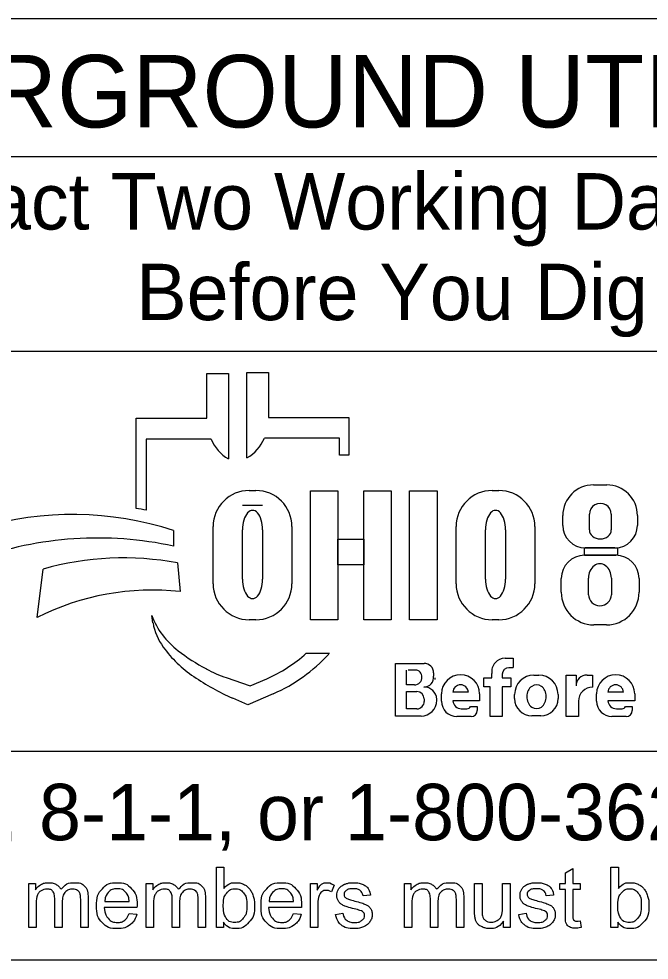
# Model space of a CAD drawing. Extents: x 0 to 36.5, y 0 to 25.3.
# Drawn here: x 3.267 to 4.831, y 2.143 to 4.48 of the extents above; entities that cross this region are included whole.
import ezdxf

# ---------------------------------------------------------------- set-up
doc = ezdxf.new("R2010")
doc.units = 0
doc.layers.add('SH_Data', color=7, linetype='Continuous')
doc.layers.add('SH_Text', color=7, linetype='Continuous')

msp = doc.modelspace()

# ---------------------------------------------------------------- linework, layer by layer
at = {"layer": 'SH_Data'}
for p, q in [((6.6275, 4.4803), (2.3775, 4.4803)), ((2.3775, 4.1387), (6.6275, 4.1387)), ((2.3775, 3.6553), (6.6275, 3.6553)), ((6.6275, 2.6607), (2.3775, 2.6607)), ((6.6275, 2.1428), (2.3775, 2.1428))]:
    msp.add_line(p, q, dxfattribs=at)
at = {"layer": 'SH_Text'}
for p, q in [((3.7335, 3.4883), (3.7335, 3.5998)), ((3.7335, 3.5998), (3.7872, 3.5998)), ((3.7872, 3.5998), (3.7872, 3.3877)), ((3.8329, 3.39), (3.8329, 3.6021)), ((3.8329, 3.6021), (3.8865, 3.6021)), ((3.8865, 3.6021), (3.8865, 3.4906)), ((3.5576, 3.2644), (3.5576, 3.4883)), ((3.5576, 3.4883), (3.7335, 3.4883)), ((3.8865, 3.4906), (4.0857, 3.4906)), ((4.0857, 3.4906), (4.0857, 3.3968)), ((3.5828, 3.4369), (3.5828, 3.26)), ((3.7439, 3.4369), (3.5828, 3.4369)), ((4.0625, 3.4392), (3.8761, 3.4392)), ((4.0625, 3.3968), (4.0625, 3.4392)), ((4.0857, 3.3968), (4.0625, 3.3968)), ((4.6931, 3.3231), (4.7258, 3.3231)), ((3.8385, 3.3091), (3.8551, 3.3091)), ((4.4416, 3.3091), (4.4581, 3.3091)), ((3.8718, 3.2721), (3.822, 3.2721)), ((4.683, 3.2111), (4.683, 3.2504)), ((4.7371, 3.2504), (4.7371, 3.2111)), ((4.6168, 3.2225), (4.6168, 3.2468)), ((4.8022, 3.2468), (4.8022, 3.2225)), ((3.6509, 3.2097), (3.6509, 3.1709)), ((3.7491, 3.0776), (3.7491, 3.2196)), ((3.822, 3.089), (3.822, 3.2114)), ((3.8718, 3.2114), (3.8718, 3.089)), ((3.9445, 3.2196), (3.9445, 3.0776)), ((4.3521, 3.0776), (4.3521, 3.2196)), ((4.425, 3.089), (4.425, 3.2114)), ((4.4748, 3.2114), (4.4748, 3.089)), ((4.5476, 3.2196), (4.5476, 3.0776)), ((4.7462, 3.1665), (4.6728, 3.1665)), ((4.671, 3.1482), (4.7483, 3.1482)), ((3.312, 2.9936), (3.3267, 3.1137)), ((3.6608, 3.1291), (3.6671, 3.0582)), ((4.6131, 3.0563), (4.6131, 3.0903)), ((4.6806, 3.0503), (4.6806, 3.0912)), ((4.7374, 3.0912), (4.7374, 3.0503)), ((4.8062, 3.0903), (4.8062, 3.0563)), ((3.5997, 2.9807), (3.5967, 2.9986)), ((3.8551, 2.9882), (3.8385, 2.9882)), ((4.4581, 2.9882), (4.4416, 2.9882)), ((4.7252, 2.9753), (4.6941, 2.9753)), ((3.98, 2.9048), (4.0375, 2.9048)), ((4.2013, 2.749), (4.2013, 2.8798)), ((4.2013, 2.8798), (4.2725, 2.8798)), ((4.4739, 2.8926), (4.4934, 2.8926)), ((4.4934, 2.8926), (4.4934, 2.8696)), ((4.2293, 2.8263), (4.2293, 2.8632)), ((4.2545, 2.8632), (4.2332, 2.8632)), ((4.2963, 2.856), (4.2963, 2.8481)), ((4.4406, 2.8442), (4.4406, 2.8546)), ((4.4667, 2.8526), (4.4667, 2.8442)), ((4.4934, 2.8691), (4.4832, 2.8691)), ((3.7816, 2.8444), (3.841, 2.8239)), ((3.841, 2.8239), (3.8821, 2.8417)), ((4.4213, 2.8212), (4.4213, 2.8442)), ((4.4213, 2.8442), (4.4406, 2.8442)), ((4.4667, 2.8442), (4.4883, 2.8442)), ((4.4883, 2.8442), (4.4883, 2.8212)), ((4.5451, 2.8508), (4.5573, 2.8508)), ((4.6254, 2.7478), (4.6254, 2.8505)), ((4.6254, 2.8505), (4.6499, 2.8505)), ((4.6499, 2.8505), (4.6499, 2.8237)), ((4.6772, 2.8505), (4.691, 2.8505)), ((4.691, 2.8505), (4.691, 2.8209)), ((4.2487, 2.8263), (4.2293, 2.8263)), ((4.2293, 2.7669), (4.2293, 2.8097)), ((4.2293, 2.8097), (4.2548, 2.8097)), ((4.3824, 2.8082), (4.3439, 2.8082)), ((4.4362, 2.8212), (4.4213, 2.8212)), ((4.4362, 2.7478), (4.4362, 2.8212)), ((4.4883, 2.8212), (4.4667, 2.8212)), ((4.4667, 2.8212), (4.4667, 2.7478)), ((4.7674, 2.8082), (4.7288, 2.8082)), ((3.835, 2.7769), (3.7976, 2.7934)), ((3.8983, 2.8044), (3.835, 2.7769)), ((4.2729, 2.7916), (4.2729, 2.7853)), ((4.3043, 2.7887), (4.3043, 2.7884)), ((4.3159, 2.7858), (4.3159, 2.8042)), ((4.4104, 2.7866), (4.344, 2.7866)), ((4.4104, 2.8042), (4.4104, 2.7866)), ((4.4973, 2.7922), (4.4973, 2.8029)), ((4.6051, 2.8029), (4.6051, 2.7922)), ((4.6559, 2.786), (4.6559, 2.7478)), ((4.7008, 2.7858), (4.7008, 2.8042)), ((4.7953, 2.7866), (4.7289, 2.7866)), ((4.7953, 2.8042), (4.7953, 2.7866)), ((4.2546, 2.7669), (4.2293, 2.7669)), ((4.3649, 2.7673), (4.379, 2.7673)), ((4.3876, 2.7729), (4.4045, 2.7729)), ((4.4045, 2.7729), (4.4045, 2.7631)), ((4.7498, 2.7673), (4.7639, 2.7673)), ((4.7725, 2.7729), (4.7894, 2.7729)), ((4.7894, 2.7729), (4.7894, 2.7631)), ((4.265, 2.749), (4.2013, 2.749)), ((4.3892, 2.7478), (4.3538, 2.7478)), ((4.4667, 2.7478), (4.4362, 2.7478)), ((4.5623, 2.7494), (4.5401, 2.7494)), ((4.6559, 2.7478), (4.6254, 2.7478)), ((4.7742, 2.7478), (4.7388, 2.7478))]:
    msp.add_line(p, q, dxfattribs=at)
for points in [[(3.991, 3.3081), (4.0589, 3.3081), (4.0589, 2.9881), (3.991, 2.9881)], [(4.1231, 3.3081), (4.1911, 3.3081), (4.1911, 2.9881), (4.1231, 2.9881)], [(4.2364, 3.3081), (4.3052, 3.3081), (4.3052, 2.9881), (4.2364, 2.9881)], [(4.0589, 3.1882), (4.1231, 3.1882), (4.1231, 3.1242), (4.0589, 3.1242)], [(4.6706, 3.1665), (4.7523, 3.1665), (4.7523, 3.1481), (4.6706, 3.1481)]]:
    msp.add_lwpolyline(points, close=True, dxfattribs=at)
for points in [[(3.7743, 2.2239), (3.7573, 2.2239), (3.7573, 2.3741), (3.7757, 2.3741), (3.7757, 2.3206)], [(4.6233, 2.2558), (4.6233, 2.3185), (4.6097, 2.3185), (4.6097, 2.3328), (4.6233, 2.3328), (4.6233, 2.3597), (4.6417, 2.3708), (4.6417, 2.3328), (4.6601, 2.3328), (4.6601, 2.3185), (4.6417, 2.3185), (4.6417, 2.2547)], [(4.7534, 2.2239), (4.7363, 2.2239), (4.7363, 2.3741), (4.7548, 2.3741), (4.7548, 2.3206)], [(3.2912, 2.2239), (3.2912, 2.3328), (3.3077, 2.3328), (3.3077, 2.3174)], [(3.5826, 2.2239), (3.5826, 2.3328), (3.5991, 2.3328), (3.5991, 2.3174)], [(3.9904, 2.2239), (3.9904, 2.3328), (4.007, 2.3328), (4.007, 2.3163)], [(4.0495, 2.3293), (4.043, 2.3122)], [(4.2236, 2.2239), (4.2236, 2.3328), (4.2401, 2.3328), (4.2401, 2.3174)], [(4.3979, 2.2654), (4.3979, 2.3328), (4.4164, 2.3328), (4.4164, 2.2724)], [(4.4676, 2.2745), (4.4676, 2.3328), (4.4861, 2.3328), (4.4861, 2.2239), (4.4696, 2.2239)], [(3.3743, 2.2871), (3.3743, 2.2239), (3.3559, 2.2239), (3.3559, 2.2946)], [(3.4388, 2.2986), (3.4388, 2.2239), (3.4203, 2.2239), (3.4203, 2.2924)], [(3.6657, 2.2871), (3.6657, 2.2239), (3.6473, 2.2239), (3.6473, 2.2946)], [(3.7301, 2.2986), (3.7301, 2.2239), (3.7117, 2.2239), (3.7117, 2.2924)], [(4.1394, 2.3046), (4.1213, 2.3022)], [(4.3067, 2.2871), (4.3067, 2.2239), (4.2883, 2.2239), (4.2883, 2.2946)], [(4.3711, 2.2986), (4.3711, 2.2239), (4.3527, 2.2239), (4.3527, 2.2924)], [(4.594, 2.3046), (4.5759, 2.3022)], [(3.3097, 2.2803), (3.3097, 2.2239), (3.2912, 2.2239)], [(3.56, 2.2736), (3.4788, 2.2736)], [(3.4799, 2.2887), (3.5406, 2.2887)], [(3.601, 2.2803), (3.601, 2.2239), (3.5826, 2.2239)], [(3.968, 2.2736), (3.8868, 2.2736)], [(3.8879, 2.2887), (3.9486, 2.2887)], [(4.0088, 2.2809), (4.0088, 2.2239), (3.9904, 2.2239)], [(4.242, 2.2803), (4.242, 2.2239), (4.2236, 2.2239)], [(3.5404, 2.2591), (3.5595, 2.2567)], [(3.9484, 2.2591), (3.9675, 2.2567)], [(4.053, 2.2564), (4.0712, 2.2593)], [(4.5076, 2.2564), (4.5258, 2.2593)], [(3.7743, 2.2375), (3.7743, 2.2239)], [(4.4696, 2.2239), (4.4696, 2.24)], [(4.6601, 2.2404), (4.6628, 2.2241)], [(4.7534, 2.2375), (4.7534, 2.2239)]]:
    msp.add_lwpolyline(points, dxfattribs=at)
for centre, radius, start, end in [((3.8353, 3.4736), 0.0985, 201.9296, 240.7469), ((3.7847, 3.476), 0.0985, 299.2531, 338.0704), ((4.6931, 3.2468), 0.0763, 90, 180), ((4.7258, 3.2468), 0.0763, 0, 90), ((3.8385, 3.2196), 0.0895, 90, 180), ((3.8551, 3.2196), 0.0895, 0, 90), ((4.4416, 3.2196), 0.0895, 90, 180), ((4.4581, 3.2196), 0.0895, 0, 90), ((3.3997, 2.4302), 0.8191, 72.1402, 106.3144), ((3.4295, 2.4554), 0.8191, 79.2074, 81.0007), ((4.6728, 3.2225), 0.056, 180, 270), ((4.7462, 3.2225), 0.056, 270, 0), ((3.4628, 2.2991), 0.8919, 77.8238, 109.8274), ((3.5267, 2.4094), 0.7322, 79.44, 105.8467), ((4.671, 3.0903), 0.0579, 90, 180), ((4.7483, 3.0903), 0.0579, 0, 90), ((3.8385, 3.0776), 0.0895, 180, 270), ((3.8551, 3.0776), 0.0895, 270, 0), ((4.4416, 3.0776), 0.0895, 180, 270), ((4.4581, 3.0776), 0.0895, 270, 0), ((3.5987, 2.4262), 0.6357, 83.8248, 116.8021), ((4.6941, 3.0563), 0.081, 180, 270), ((4.7252, 3.0563), 0.081, 270, 0), ((3.7841, 3.0707), 0.2008, 201.0457, 232.5314), ((3.741, 3.0048), 0.1433, 189.6817, 216.0884), ((3.8747, 3.1022), 0.3088, 216.0884, 235.7167), ((3.9766, 3.3219), 0.5173, 232.5314, 241.794), ((3.7387, 3.1722), 0.3602, 293.4582, 312.0712), ((3.7387, 3.1722), 0.401, 293.4582, 317.8286), ((4.2725, 2.856), 0.0238, 0, 90), ((4.4739, 2.859), 0.0335, 90, 187.5187), ((3.8914, 3.1631), 0.3371, 241.794, 250.9821), ((4.2505, 2.8463), 0.0169, 357.8325, 90), ((4.4832, 2.8526), 0.0165, 90, 180), ((4.0412, 3.3465), 0.6044, 235.7167, 246.2325), ((4.2487, 2.845), 0.0187, 270, 2.0582), ((4.2721, 2.8453), 0.0243, 270, 6.6529), ((4.2827, 2.8438), 0.0175, 347.4023, 0), ((4.3631, 2.8042), 0.0473, 0, 180), ((4.5451, 2.8029), 0.0478, 90, 180), ((4.5573, 2.8029), 0.0478, 0, 90), ((4.6768, 2.8237), 0.0269, 89.2449, 180), ((4.7481, 2.8042), 0.0473, 0, 180), ((4.2548, 2.7916), 0.0181, 0, 90), ((4.2722, 2.7889), 0.0321, 4.0748, 90), ((4.3632, 2.8072), 0.0193, 2.9632, 177.0368), ((4.6908, 2.786), 0.0349, 89.6033, 180), ((4.7481, 2.8072), 0.0193, 2.9632, 177.0368), ((4.2546, 2.7853), 0.0184, 270, 0), ((4.265, 2.7884), 0.0393, 270, 0), ((4.2714, 2.7887), 0.033, 0, 11.7502), ((4.3538, 2.7858), 0.038, 180, 270), ((4.3649, 2.7883), 0.021, 184.827, 270), ((4.5401, 2.7922), 0.0428, 180, 270), ((4.5623, 2.7922), 0.0428, 270, 0), ((4.7388, 2.7858), 0.038, 180, 270), ((4.7498, 2.7883), 0.021, 184.827, 270), ((4.379, 2.7767), 0.00938, 270, 335.9979), ((4.3892, 2.7631), 0.0152, 270, 0), ((4.7639, 2.7767), 0.00938, 270, 335.9979), ((4.7742, 2.7631), 0.0152, 270, 0)]:
    msp.add_arc(centre, radius, start, end, dxfattribs=at)
for centre, major_axis, ratio, start_param, end_param in [((4.71, 3.2504), (0.0271, 0), 0.969373, 0, 3.141593), ((3.8469, 3.2114), (0, 0.0484), 0.514403, 4.712389, 7.853982), ((4.4499, 3.2114), (0, 0.0484), 0.514403, 4.712389, 7.853982), ((4.71, 3.2111), (0.0271, 0), 0.818453, 3.141593, 6.283185), ((4.709, 3.0912), (0, 0.0358), 0.794529, 4.712389, 7.853982), ((3.8469, 3.089), (0, 0.0484), 0.514403, 1.570796, 4.712389), ((4.4499, 3.089), (0, 0.0484), 0.514403, 1.570796, 4.712389), ((4.709, 3.0503), (0.0284, 0), 0.959837, 3.141593, 6.283185), ((4.5517, 2.7976), (0, 0.029), 0.832186, 4.712389, 7.853982), ((4.5517, 2.7976), (0, 0.0302), 0.797287, 1.570796, 4.712389)]:
    msp.add_ellipse(centre, major_axis=major_axis, ratio=ratio, start_param=start_param, end_param=end_param, dxfattribs=at)
for points in [[(3.3077, 2.3174), (3.3128, 2.3254), (3.3214, 2.3303), (3.3299, 2.3352), (3.3407, 2.3352), (3.3528, 2.3352), (3.3606, 2.3301), (3.3683, 2.3251), (3.3715, 2.3161), (3.3844, 2.3352), (3.4051, 2.3352), (3.4213, 2.3352), (3.43, 2.3262), (3.4388, 2.3172), (3.4388, 2.2986)], [(3.3559, 2.2946), (3.3559, 2.3069), (3.3514, 2.313), (3.3469, 2.3191), (3.3366, 2.3191), (3.3288, 2.3191), (3.3222, 2.315), (3.3156, 2.311), (3.3126, 2.3031), (3.3097, 2.2952), (3.3097, 2.2803)], [(3.4203, 2.2924), (3.4203, 2.3035), (3.4185, 2.3083), (3.4168, 2.3132), (3.412, 2.3162), (3.4073, 2.3191), (3.401, 2.3191), (3.3895, 2.3191), (3.3819, 2.3115), (3.3743, 2.3039), (3.3743, 2.2871)], [(3.5595, 2.2567), (3.555, 2.24), (3.5428, 2.2307), (3.5306, 2.2215), (3.5117, 2.2215), (3.4878, 2.2215), (3.4738, 2.2362), (3.4598, 2.2509), (3.4598, 2.2774), (3.4598, 2.3049), (3.474, 2.32), (3.4881, 2.3352), (3.5106, 2.3352), (3.5324, 2.3352), (3.5463, 2.3203), (3.5601, 2.3055), (3.5601, 2.2785), (3.5601, 2.2769), (3.56, 2.2736)], [(3.5406, 2.2887), (3.5394, 2.3025), (3.5337, 2.3094), (3.5249, 2.3201), (3.5108, 2.3201), (3.4981, 2.3201), (3.4894, 2.3115), (3.4808, 2.303), (3.4799, 2.2887)], [(3.5991, 2.3174), (3.6042, 2.3254), (3.6127, 2.3303), (3.6212, 2.3352), (3.6321, 2.3352), (3.6442, 2.3352), (3.6519, 2.3301), (3.6597, 2.3251), (3.6628, 2.3161), (3.6758, 2.3352), (3.6965, 2.3352), (3.7127, 2.3352), (3.7214, 2.3262), (3.7301, 2.3172), (3.7301, 2.2986)], [(3.6473, 2.2946), (3.6473, 2.3069), (3.6428, 2.313), (3.6383, 2.3191), (3.628, 2.3191), (3.6202, 2.3191), (3.6136, 2.315), (3.607, 2.311), (3.604, 2.3031), (3.601, 2.2952), (3.601, 2.2803)], [(3.7117, 2.2924), (3.7117, 2.3035), (3.7099, 2.3083), (3.7081, 2.3132), (3.7034, 2.3162), (3.6987, 2.3191), (3.6923, 2.3191), (3.6809, 2.3191), (3.6733, 2.3115), (3.6657, 2.3039), (3.6657, 2.2871)], [(3.7741, 2.2792), (3.7741, 2.2596), (3.7794, 2.2509), (3.7881, 2.2366), (3.8029, 2.2366), (3.815, 2.2366), (3.8238, 2.2471), (3.8326, 2.2576), (3.8326, 2.2784), (3.8326, 2.2998), (3.8241, 2.3099), (3.8157, 2.3201), (3.8038, 2.3201), (3.7917, 2.3201), (3.7829, 2.3096), (3.7741, 2.299), (3.7741, 2.2792)], [(3.7757, 2.3206), (3.7874, 2.3352), (3.8055, 2.3352), (3.8155, 2.3352), (3.8245, 2.3311), (3.8335, 2.3271), (3.8392, 2.3198), (3.845, 2.3124), (3.8483, 2.3021), (3.8516, 2.2918), (3.8516, 2.28), (3.8516, 2.252), (3.8378, 2.2368), (3.8239, 2.2215), (3.8046, 2.2215), (3.7853, 2.2215), (3.7743, 2.2375)], [(3.9675, 2.2567), (3.963, 2.24), (3.9508, 2.2307), (3.9386, 2.2215), (3.9196, 2.2215), (3.8958, 2.2215), (3.8818, 2.2362), (3.8678, 2.2509), (3.8678, 2.2774), (3.8678, 2.3049), (3.882, 2.32), (3.8961, 2.3352), (3.9186, 2.3352), (3.9404, 2.3352), (3.9543, 2.3203), (3.9681, 2.3055), (3.9681, 2.2785), (3.9681, 2.2769), (3.968, 2.2736)], [(3.9486, 2.2887), (3.9474, 2.3025), (3.9417, 2.3094), (3.9328, 2.3201), (3.9188, 2.3201), (3.9061, 2.3201), (3.8974, 2.3115), (3.8888, 2.303), (3.8879, 2.2887)], [(4.007, 2.3163), (4.0133, 2.3278), (4.0187, 2.3315), (4.0241, 2.3352), (4.0305, 2.3352), (4.0398, 2.3352), (4.0495, 2.3293)], [(4.043, 2.3122), (4.0363, 2.3162), (4.0295, 2.3162), (4.0235, 2.3162), (4.0187, 2.3125), (4.0139, 2.3089), (4.0119, 2.3024), (4.0088, 2.2926), (4.0088, 2.2809)], [(4.1213, 2.3022), (4.1201, 2.3106), (4.1142, 2.3153), (4.1083, 2.3201), (4.0975, 2.3201), (4.0848, 2.3201), (4.0794, 2.3159), (4.0739, 2.3116), (4.0739, 2.306), (4.0739, 2.3024), (4.0762, 2.2995), (4.0785, 2.2966), (4.0833, 2.2946), (4.086, 2.2936), (4.0996, 2.2899), (4.1192, 2.2847), (4.1269, 2.2813), (4.1347, 2.278), (4.1391, 2.2717), (4.1435, 2.2653), (4.1435, 2.2559), (4.1435, 2.2467), (4.1381, 2.2386), (4.1327, 2.2304), (4.1226, 2.226), (4.1124, 2.2215), (4.0996, 2.2215), (4.0784, 2.2215), (4.0672, 2.2303), (4.0561, 2.2391), (4.053, 2.2564)], [(4.0712, 2.2593), (4.0727, 2.2483), (4.0798, 2.2425), (4.0868, 2.2366), (4.0995, 2.2366), (4.1122, 2.2366), (4.1184, 2.2418), (4.1245, 2.247), (4.1245, 2.254), (4.1245, 2.2602), (4.1191, 2.2638), (4.1153, 2.2663), (4.1002, 2.2701), (4.0799, 2.2752), (4.072, 2.2789), (4.0642, 2.2827), (4.0601, 2.2893), (4.0561, 2.2959), (4.0561, 2.3038), (4.0561, 2.3111), (4.0594, 2.3173), (4.0628, 2.3235), (4.0685, 2.3276), (4.0728, 2.3308), (4.0803, 2.333), (4.0877, 2.3352), (4.0962, 2.3352), (4.109, 2.3352), (4.1187, 2.3315), (4.1284, 2.3278), (4.133, 2.3215), (4.1377, 2.3152), (4.1394, 2.3046)], [(4.2401, 2.3174), (4.2452, 2.3254), (4.2537, 2.3303), (4.2622, 2.3352), (4.2731, 2.3352), (4.2852, 2.3352), (4.2929, 2.3301), (4.3007, 2.3251), (4.3038, 2.3161), (4.3168, 2.3352), (4.3375, 2.3352), (4.3537, 2.3352), (4.3624, 2.3262), (4.3711, 2.3172), (4.3711, 2.2986)], [(4.2883, 2.2946), (4.2883, 2.3069), (4.2838, 2.313), (4.2793, 2.3191), (4.269, 2.3191), (4.2612, 2.3191), (4.2546, 2.315), (4.248, 2.311), (4.245, 2.3031), (4.242, 2.2952), (4.242, 2.2803)], [(4.3527, 2.2924), (4.3527, 2.3035), (4.3509, 2.3083), (4.3491, 2.3132), (4.3444, 2.3162), (4.3397, 2.3191), (4.3333, 2.3191), (4.3219, 2.3191), (4.3143, 2.3115), (4.3067, 2.3039), (4.3067, 2.2871)], [(4.5759, 2.3022), (4.5747, 2.3106), (4.5688, 2.3153), (4.5629, 2.3201), (4.5521, 2.3201), (4.5394, 2.3201), (4.5339, 2.3159), (4.5285, 2.3116), (4.5285, 2.306), (4.5285, 2.3024), (4.5308, 2.2995), (4.533, 2.2966), (4.5378, 2.2946), (4.5406, 2.2936), (4.5542, 2.2899), (4.5737, 2.2847), (4.5815, 2.2813), (4.5893, 2.278), (4.5937, 2.2717), (4.5981, 2.2653), (4.5981, 2.2559), (4.5981, 2.2467), (4.5927, 2.2386), (4.5873, 2.2304), (4.5772, 2.226), (4.567, 2.2215), (4.5542, 2.2215), (4.5329, 2.2215), (4.5218, 2.2303), (4.5107, 2.2391), (4.5076, 2.2564)], [(4.5258, 2.2593), (4.5273, 2.2483), (4.5343, 2.2425), (4.5414, 2.2366), (4.554, 2.2366), (4.5668, 2.2366), (4.5729, 2.2418), (4.5791, 2.247), (4.5791, 2.254), (4.5791, 2.2602), (4.5736, 2.2638), (4.5698, 2.2663), (4.5548, 2.2701), (4.5345, 2.2752), (4.5266, 2.2789), (4.5188, 2.2827), (4.5147, 2.2893), (4.5107, 2.2959), (4.5107, 2.3038), (4.5107, 2.3111), (4.514, 2.3173), (4.5173, 2.3235), (4.5231, 2.3276), (4.5274, 2.3308), (4.5348, 2.333), (4.5423, 2.3352), (4.5508, 2.3352), (4.5636, 2.3352), (4.5733, 2.3315), (4.583, 2.3278), (4.5876, 2.3215), (4.5922, 2.3152), (4.594, 2.3046)], [(4.7532, 2.2792), (4.7532, 2.2596), (4.7585, 2.2509), (4.7672, 2.2366), (4.782, 2.2366), (4.7941, 2.2366), (4.8029, 2.2471), (4.8116, 2.2576), (4.8116, 2.2784), (4.8116, 2.2998), (4.8032, 2.3099), (4.7948, 2.3201), (4.7828, 2.3201), (4.7708, 2.3201), (4.762, 2.3096), (4.7532, 2.299), (4.7532, 2.2792)], [(4.7548, 2.3206), (4.7664, 2.3352), (4.7846, 2.3352), (4.7946, 2.3352), (4.8036, 2.3311), (4.8125, 2.3271), (4.8183, 2.3198), (4.8241, 2.3124), (4.8274, 2.3021), (4.8306, 2.2918), (4.8306, 2.28), (4.8306, 2.252), (4.8168, 2.2368), (4.803, 2.2215), (4.7836, 2.2215), (4.7644, 2.2215), (4.7534, 2.2375)], [(3.4788, 2.2736), (3.4799, 2.2557), (3.489, 2.2462), (3.4981, 2.2366), (3.5117, 2.2366), (3.5219, 2.2366), (3.5291, 2.242), (3.5362, 2.2473), (3.5404, 2.2591)], [(3.8868, 2.2736), (3.8879, 2.2557), (3.897, 2.2462), (3.9061, 2.2366), (3.9197, 2.2366), (3.9299, 2.2366), (3.937, 2.242), (3.9442, 2.2473), (3.9484, 2.2591)], [(4.4164, 2.2724), (4.4164, 2.258), (4.4175, 2.253), (4.4192, 2.2457), (4.4249, 2.2416), (4.4305, 2.2374), (4.4388, 2.2374), (4.4471, 2.2374), (4.4543, 2.2417), (4.4616, 2.2459), (4.4646, 2.2533), (4.4676, 2.2606), (4.4676, 2.2745)], [(4.4696, 2.24), (4.4569, 2.2215), (4.4351, 2.2215), (4.4255, 2.2215), (4.4171, 2.2252), (4.4088, 2.2289), (4.4047, 2.2345), (4.4007, 2.2401), (4.3991, 2.2482), (4.3979, 2.2536), (4.3979, 2.2654)], [(4.6628, 2.2241), (4.655, 2.2224), (4.6488, 2.2224), (4.6388, 2.2224), (4.6333, 2.2256), (4.6278, 2.2288), (4.6255, 2.234), (4.6233, 2.2392), (4.6233, 2.2558)], [(4.6417, 2.2547), (4.6417, 2.2468), (4.6427, 2.2445), (4.6436, 2.2423), (4.6458, 2.2409), (4.648, 2.2396), (4.6521, 2.2396), (4.6551, 2.2396), (4.6601, 2.2404)]]:
    msp.add_open_spline(points, degree=3, dxfattribs=at)

# ---------------------------------------------------------------- texts
for s, height, p in [('UNDERGROUND UTILITIES', 0.18, (2.5057, 4.2106)), ('Contact Two Working Days', 0.14, (2.7972, 3.9571)), ('Before You Dig', 0.14, (3.5583, 3.7321)), ('OHIO811, 8-1-1, or 1-800-362-2764', 0.14, (2.422, 2.4406))]:
    msp.add_text(s, height=height, dxfattribs=at).set_placement(p)

doc.saveas('drawing.dxf')
